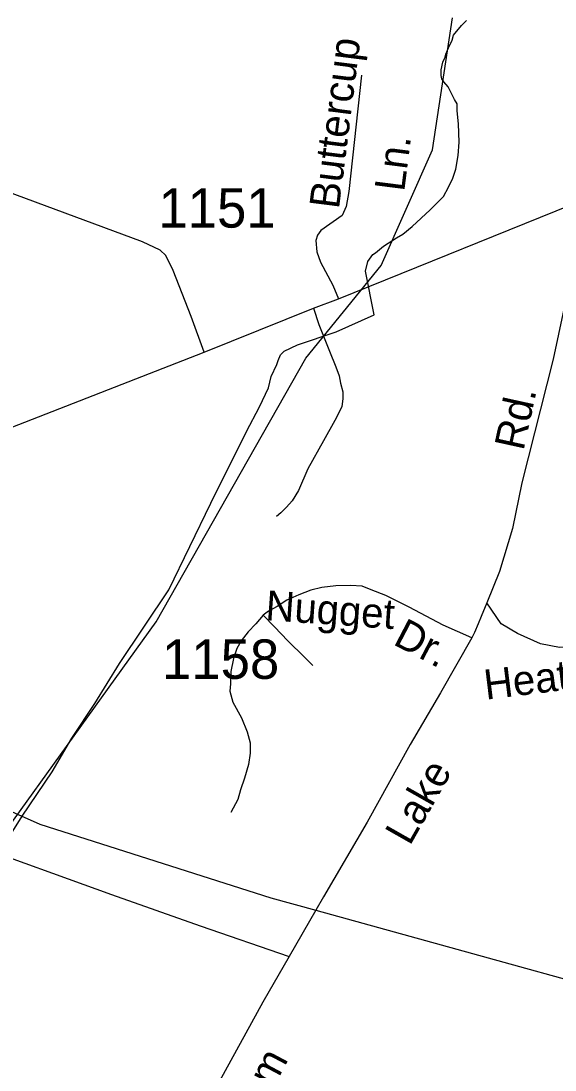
# Model space of a CAD drawing. Extents: x 2260773 to 2342389, y 552869 to 618546.
# Drawn here: x 2283170 to 2284865, y 571861 to 575188 of the extents above; entities that cross this region are included whole.
import ezdxf

# ---------------------------------------------------------------- set-up
doc = ezdxf.new("R2010")
doc.units = 0
for name, color, linetype in [('Exist Boundary Political Urban Extension UEB', 7, 'Continuous'), ('Exist Hydrographic Misc Water Feature', 7, 'Continuous'), ('Exist Road Non-System Type 51', 7, 'Continuous'), ('Exist Road Non-System Type 51 Label', 7, 'Continuous'), ('Exist Road Primary US Attributed', 7, 'Continuous'), ('Exist Road Secondary Type 51 Attributed', 7, 'Continuous'), ('Exist Road Secondary Type 51 Label', 7, 'Continuous'), ('Exist Road Secondary Type 51 Number Label', 7, 'Continuous')]:
    doc.layers.add(name, color=color, linetype=linetype)

msp = doc.modelspace()

# ---------------------------------------------------------------- linework, layer by layer
at = {"layer": 'Exist Boundary Political Urban Extension UEB'}
for points in [[(2280848.5, 572968.9), (2281065.3, 572906.9), (2281664.8, 572940.2), (2282197.7, 572973.5), (2282630.6, 572906.9), (2283230.1, 572640.5), (2283962.9, 572407.4), (2284105.3, 572368)], [(2284105.3, 572368), (2285528.2, 571974.5), (2286127.7, 571874.6), (2286722.8, 572028.8)]]:
    msp.add_lwpolyline(points, dxfattribs=at)
at = {"layer": 'Exist Hydrographic Misc Water Feature'}
for points in [[(2280315.7, 570810.8), (2281300.8, 571368), (2281988.8, 571816.5), (2282618.9, 572056.4), (2282841.8, 572232.2), (2283598.8, 573282.8), (2284073.7, 574119.3), (2284312.8, 574412.9), (2284475.8, 574780.2), (2284538.8, 575198.7)], [(2283128.4, 572593.8), (2283173.5, 572666.1), (2283268.3, 572806.7), (2283331.2, 572913.3), (2283404.4, 573023.9), (2283483, 573150.8), (2283638.6, 573384), (2283771.9, 573659.1), (2283885.9, 573886.1), (2283926.9, 573964.7), (2283954.8, 574024.5), (2283964.2, 574060.8), (2283982.1, 574098.7), (2283985.8, 574111.1), (2283993.3, 574129), (2284005.2, 574141), (2284046.9, 574161.5), (2284170.5, 574202.5), (2284290.1, 574255.9), (2284262.6, 574395.4), (2284270.6, 574425.5), (2284286.2, 574447.5), (2284294.4, 574453.5), (2284319.8, 574474), (2284361.6, 574500.2), (2284381.5, 574512.6), (2284411, 574536.9), (2284439.3, 574563.1), (2284468.7, 574589.1), (2284490.6, 574611.3), (2284510.5, 574631.4), (2284526.3, 574661.5), (2284539.8, 574689.8), (2284549.6, 574718), (2284557.4, 574761.8), (2284560.5, 574803.9), (2284558.3, 574861.9), (2284553.7, 574903.9), (2284553.5, 574925.8), (2284545.8, 574939.6), (2284525.2, 574979.6), (2284511.3, 574995.5), (2284505.2, 575005.3), (2284503.1, 575015.4), (2284503.1, 575033.2), (2284508.8, 575057.5), (2284516.2, 575073.4), (2284518.3, 575083.2), (2284526.3, 575103.5), (2284538, 575127.7), (2284541.9, 575143.4), (2284567.3, 575174), (2284583.1, 575189.9)]]:
    msp.add_lwpolyline(points, dxfattribs=at)
at = {"layer": 'Exist Road Non-System Type 51'}
for points in [[(2284250, 575016.6), (2284209.7, 574647.7), (2284202.2, 574600), (2284188.8, 574571.6), (2284121.7, 574523.8), (2284111.2, 574508.9), (2284105.2, 574492.5), (2284108.2, 574456.6), (2284120.2, 574423.8), (2284159, 574350.6), (2284176.9, 574307.3)], [(2284098.1, 574277.7), (2284114.9, 574225.9), (2284149.3, 574140.8), (2284168.7, 574091.5), (2284179.1, 574063.2), (2284183.6, 574039.3), (2284191, 574012.4), (2284191, 573991.5), (2284188.1, 573964.6), (2284165.7, 573921.3), (2284129.9, 573857.1), (2284080.6, 573767.5), (2284050.8, 573698.8), (2284029.9, 573666), (2284012, 573646.6), (2283994.1, 573628.7), (2283980.6, 573616.7)], [(2285337.6, 573271.4), (2285191.2, 573251.3), (2285026.6, 573220.7), (2284940.5, 573205.3), (2284879.2, 573201.5), (2284818, 573213), (2284745.3, 573245.6), (2284693.6, 573276.2), (2284647.6, 573343.2)], [(2283938.2, 573303.7), (2283914.6, 573276.2), (2283890.4, 573250.7), (2283868.7, 573222.6), (2283854.6, 573198.3), (2283844.4, 573166.4), (2283835.5, 573125.6), (2283834.2, 573086), (2283833, 573063), (2283842.5, 573027.9), (2283869.3, 572978.1), (2283887.2, 572933.4), (2283897.4, 572899), (2283897.4, 572865.8), (2283892.3, 572830), (2283879.5, 572786.6), (2283866.8, 572749.6), (2283857.8, 572718.9), (2283836.1, 572678.1)], [(2283938.2, 573303.7), (2283974.6, 573267.3), (2284016.7, 573222.6), (2284069, 573170.2), (2284095.8, 573144.7)]]:
    msp.add_lwpolyline(points, dxfattribs=at)
at = {"layer": 'Exist Road Primary US Attributed'}
msp.add_line((2282923.1, 573815.8), (2283750.8, 574137.8), dxfattribs=at)
msp.add_lwpolyline([(2283750.8, 574137.8), (2284098.1, 574277.7), (2284176.9, 574307.3), (2284967.3, 574626.3)], dxfattribs=at)
at = {"layer": 'Exist Road Secondary Type 51 Attributed'}
for points in [[(2283750.8, 574137.8), (2283709.8, 574250.6), (2283653.1, 574396.9), (2283629.2, 574444.7), (2283611.3, 574461.1), (2283555.6, 574488.4), (2282261.3, 574966.5)], [(2284967.3, 574626.3), (2284858.1, 574115.4), (2284758.9, 573723.5), (2284729.9, 573578.8), (2284687.8, 573442.8), (2284647.6, 573343.2), (2284629.8, 573299.8), (2284620.9, 573276.8), (2284609.4, 573248.8), (2284600.4, 573232.2)], [(2284600.4, 573232.2), (2284509.8, 573271.7), (2284401.4, 573329.2), (2284327.4, 573366.2), (2284281.5, 573384.1), (2284252.1, 573395.6), (2284215.1, 573398.1), (2284169.2, 573396.8), (2284124.5, 573391.7), (2284090.1, 573382.8), (2284051.8, 573368.8), (2284013.5, 573350.9), (2283982.9, 573331.7), (2283954.8, 573316.4), (2283938.2, 573303.7)], [(2284600.4, 573232.2), (2284501.6, 573057.9), (2284405.2, 572893.3), (2284268.1, 572646.8), (2284129.6, 572410), (2284105.3, 572368), (2284020.5, 572221.7)], [(2280508.6, 572815.6), (2280763.2, 572741.7), (2280907.9, 572714.8), (2280997.5, 572701.4), (2281154.2, 572688), (2281318.3, 572692.4), (2281451.1, 572716.3), (2281789.6, 572773.2), (2281963.3, 572790.7), (2282065.1, 572811.6), (2282182.9, 572816.8), (2282308.5, 572811.2), (2282465.1, 572773.6), (2282627.8, 572718.6), (2282994.2, 572584.9), (2283457.6, 572418.4), (2283738.5, 572318.7), (2284020.5, 572221.7)], [(2284020.5, 572221.7), (2283936.9, 572076.8), (2283799.8, 571825.9), (2283585.4, 571405.9), (2283381.3, 570992.3), (2283285.6, 570830.1), (2283232, 570754.8), (2283182.2, 570691), (2283160.6, 570665.1)]]:
    msp.add_lwpolyline(points, dxfattribs=at)

# ---------------------------------------------------------------- texts
at = {"layer": 'Exist Road Non-System Type 51 Label'}
for s, rotation, p in [('Buttercup', 82.7701, (2284178.7, 574589.8)), ('Ln.', 82.7701, (2284385.8, 574645)), ('Heather', 6.9677, (2284644.9, 573035.6))]:
    msp.add_text(s, height=95, rotation=rotation, dxfattribs=at).set_placement(p)
at = {"layer": 'Exist Road Secondary Type 51 Label'}
for s, rotation, p in [('Rd.', 77.6585, (2284764.2, 573822.9)), ('Nugget', 356.0211, (2283943.8, 573288.1)), ('Dr.', 332.4365, (2284347.1, 573212.9)), ('Lake', 60.4239, (2284403.6, 572569.9)), ('Durham', 62.0521, (2283808.1, 571496.7))]:
    msp.add_text(s, height=95, rotation=rotation, dxfattribs=at).set_placement(p)
at = {"layer": 'Exist Road Secondary Type 51 Number Label'}
for s, p in [('1151', (2283606.1, 574533)), ('1158', (2283617.6, 573101.9))]:
    msp.add_text(s, height=125, dxfattribs=at).set_placement(p)

doc.saveas('drawing.dxf')
